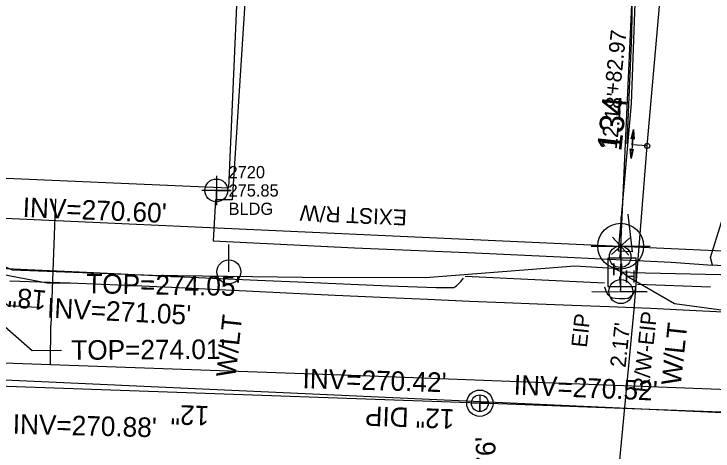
# Model space of a CAD drawing. Extents: x 2100323 to 2109811, y 740376 to 749755.
# Drawn here: x 2105501.9 to 2105644.7, y 741510.8 to 741600.1 of the extents above; entities that cross this region are included whole.
import ezdxf

# ---------------------------------------------------------------- set-up
doc = ezdxf.new("R2010")
doc.units = 0
for name, color, linetype in [('Cogo Default Point CELL', 7, 'Continuous'), ('COGO Default Point Number', 7, 'Continuous'), ('Exist Building', 7, 'Continuous'), ('Exist Building Cogo Elevation', 7, 'Continuous'), ('Exist Building Cogo Number', 7, 'Continuous'), ('Exist Building Cogo Point CELL', 7, 'Continuous'), ('Exist Horizontal Alignment', 7, 'Continuous'), ('Exist Other Culture Fence Line', 7, 'Continuous'), ('Exist Other Culture Gate', 7, 'Continuous'), ('Exist Property Corner CELL', 7, 'Continuous'), ('Exist Property Iron Pin CELL', 7, 'Continuous'), ('Exist Property Iron Pin Text', 7, 'Continuous'), ('Exist Property Line', 7, 'Continuous'), ('Exist Property Line Text', 7, 'Continuous'), ('Exist Property Tie Line Text', 7, 'Continuous'), ('Exist Right of Way Line', 7, 'Continuous'), ('Exist Right of Way Line Text', 7, 'Continuous'), ('Exist Roads Curbs', 7, 'Continuous'), ('Exist Roads EOP', 7, 'Continuous'), ('Exist Roads EOP Other', 7, 'Continuous'), ('Exist Structure Minor Catch Basin Top Elevation', 7, 'Continuous'), ('Exist Structure Minor Pipes RCP 18 Inch Invert', 7, 'Continuous'), ('Exist Structure Minor Pipes RCP 18 Inch Leader', 7, 'Continuous'), ('Exist Structure Minor Pipes RCP 18 Inch Text', 7, 'Continuous'), ('Exist Utilities Gas Change of Service SUE CELL', 7, 'Continuous'), ('Exist Utilities Gas UG Line SUE LOS B', 7, 'Continuous'), ('Exist Utilities Gas UG Line SUE LOS C', 7, 'Continuous'), ('Exist Utilities Other Pole Located Topo Text', 7, 'Continuous'), ('Exist Utilities Power Joint Use Telephone CELL', 7, 'Continuous'), ('Exist Utilities Power Pole CELL', 7, 'Continuous'), ('Exist Utilities Sanitary Sewer Manhole CELL', 7, 'Continuous'), ('Exist Utilities Sanitary Sewer Manhole Text', 7, 'Continuous'), ('Exist Utilities Sanitary Sewer UG Line', 7, 'Continuous'), ('Exist Utilities Sanitary Sewer UG Line Invert Elevation', 7, 'Continuous'), ('Exist Utilities Sanitary Sewer UG Line Text', 7, 'Continuous'), ('Exist Utilities TV Hand Hole CELL', 7, 'Continuous'), ('Exist Utilities TV UG Cable SUE LOS B', 7, 'Continuous'), ('Exist Utilities Water UG Line SUE LOS B', 7, 'Continuous')]:
    doc.layers.add(name, color=color, linetype=linetype)

msp = doc.modelspace()

# ---------------------------------------------------------------- linework, layer by layer
at = {"layer": 'Cogo Default Point CELL'}
for points in [[(2105625.85, 741558.64), (2105625.85, 741552.64)], [(2105619.85, 741552.64), (2105625.85, 741552.64)], [(2105625.85, 741552.64), (2105631.85, 741552.64)], [(2105625.85, 741552.64), (2105625.85, 741546.64)]]:
    msp.add_lwpolyline(points, dxfattribs=at)
msp.add_circle((2105625.85, 741552.64), 4.69, dxfattribs=at)
at = {"layer": 'Exist Building'}
msp.add_lwpolyline([(2105545.78, 741564.54), (2105550.54, 741673.25), (2105482.98, 741676.21), (2105478.21, 741567.5)], close=True, dxfattribs=at)
msp.add_lwpolyline([(2105627.15, 741573.57), (2105628.14, 741595.84), (2105628.48, 741616.26), (2105629.3, 741632.12), (2105629.94, 741650.5), (2105630.8, 741666.82), (2105631.43, 741673.37)], dxfattribs=at)
at = {"layer": 'Exist Building Cogo Point CELL'}
msp.add_lwpolyline([(2105543.23, 741567.03), (2105543.23, 741561.03), (2105543.23, 741564.03), (2105546.23, 741564.03), (2105540.23, 741564.03)], dxfattribs=at)
msp.add_circle((2105543.23, 741564.03), 2.34, dxfattribs=at)
at = {"layer": 'Exist Horizontal Alignment'}
msp.add_line((2105442.44, 741527.92), (2105877.12, 741508.21), dxfattribs=at)
at = {"layer": 'Exist Other Culture Fence Line'}
msp.add_lwpolyline([(2105628.25, 741551.48), (2105625.43, 741551.61), (2105628.08, 741581.82), (2105629.69, 741626.66), (2105633.02, 741680.11), (2105610.68, 741680.4), (2105612.37, 741710.75), (2105612.12, 741724.1), (2105613.19, 741740.31), (2105616.27, 741761.72), (2105642.19, 741758.96)], dxfattribs=at)
at = {"layer": 'Exist Other Culture Gate'}
msp.add_lwpolyline([(2105628.25, 741551.48), (2105627.39, 741559.15)], dxfattribs=at)
at = {"layer": 'Exist Property Corner CELL'}
msp.add_line((2105625.85, 741552.64), (2105625.85, 741552.64), dxfattribs=at)
msp.add_lwpolyline([(2105627.53, 741550.79), (2105624.17, 741554.49), (2105625.85, 741552.64), (2105624, 741550.95), (2105627.7, 741554.32)], dxfattribs=at)
at = {"layer": 'Exist Property Iron Pin CELL'}
for radius in [2.2, 0.0707]:
    msp.add_circle((2105625.75, 741550.47), radius, dxfattribs=at)
at = {"layer": 'Exist Property Line'}
for p, q in [((2105625.85, 741552.64), (2105631.31, 741670.03)), ((2105625.75, 741550.47), (2105625.85, 741552.64))]:
    msp.add_line(p, q, dxfattribs=at)
at = {"layer": 'Exist Right of Way Line'}
msp.add_line((2105478.64, 741559.31), (2105771.44, 741546.04), dxfattribs=at)
at = {"layer": 'Exist Roads Curbs'}
for points in [[(2105494.79, 741548.32), (2105504.65, 741547.84), (2105516.71, 741547.29), (2105529.36, 741546.72), (2105541, 741546.19), (2105551.66, 741545.69), (2105561.54, 741545.25), (2105570.69, 741544.87), (2105578.48, 741544.56), (2105584.27, 741544.35), (2105588.15, 741544.22), (2105590.61, 741544.17), (2105591.73, 741544.2), (2105591.99, 741544.3), (2105592.32, 741544.54), (2105593.18, 741545.44), (2105593.71, 741546.1)], [(2105628.88, 741544.19), (2105628.71, 741543.59), (2105628.55, 741543.17), (2105628.47, 741543.01), (2105628.28, 741542.75), (2105628.06, 741542.5), (2105627.81, 741542.26), (2105627.59, 741542.08), (2105627.39, 741541.96), (2105627.25, 741541.92), (2105626.67, 741541.88), (2105625.7, 741541.89), (2105624.75, 741541.94), (2105624.22, 741541.99), (2105624.12, 741542.02), (2105623.99, 741542.11), (2105623.79, 741542.24), (2105623.54, 741542.42), (2105623.42, 741542.53), (2105623.31, 741542.66), (2105623.11, 741542.97), (2105622.9, 741543.41), (2105622.67, 741544.03), (2105622.58, 741544.28)]]:
    msp.add_lwpolyline(points, dxfattribs=at)
at = {"layer": 'Exist Roads EOP'}
msp.add_lwpolyline([(2105501.01, 741545.53), (2105507.1, 741545.33), (2105513.38, 741545.11), (2105519.73, 741544.87), (2105526.52, 741544.59), (2105534.1, 741544.23), (2105542.38, 741543.82), (2105550.7, 741543.42), (2105558.95, 741543.03), (2105567.51, 741542.65), (2105576.74, 741542.22), (2105586.39, 741541.77), (2105594.94, 741541.39), (2105602.13, 741541.09), (2105608.83, 741540.83), (2105615.93, 741540.56), (2105623.49, 741540.27), (2105631.92, 741539.93), (2105641.3, 741539.5), (2105650.95, 741539.04)], dxfattribs=at)
at = {"layer": 'Exist Roads EOP Other'}
for p, q in [((2105594.04, 741546.5), (2105622.55, 741545.17)), ((2105629.28, 741544.88), (2105644.23, 741544.33))]:
    msp.add_line(p, q, dxfattribs=at)
for points in [[(2105550.01, 741661.23), (2105551.24, 741661.19), (2105550.57, 741634.09), (2105548.97, 741601.3), (2105546.93, 741569.53), (2105546.43, 741562.13), (2105543.08, 741562.08)], [(2105673.38, 741546.76), (2105644.61, 741548.75), (2105644.22, 741550.34), (2105648.65, 741564.57)], [(2105543.08, 741562.08), (2105542.57, 741553.75), (2105571.43, 741552.27), (2105596.13, 741551.26), (2105614.98, 741550.38), (2105636.14, 741549.36), (2105644.61, 741548.75)]]:
    msp.add_lwpolyline(points, dxfattribs=at)
at = {"layer": 'Exist Structure Minor Catch Basin Top Elevation'}
for points in [[(2105486.04, 741548.43), (2105505.59, 741531.34), (2105511.59, 741531.38)], [(2105493.58, 741548), (2105508.66, 741545.15), (2105514.66, 741545.04)]]:
    msp.add_lwpolyline(points, dxfattribs=at)
at = {"layer": 'Exist Structure Minor Pipes RCP 18 Inch Leader'}
msp.add_lwpolyline([(2105490.87, 741548.53), (2105500.69, 741540.48), (2105506.68, 741540.17)], dxfattribs=at)
at = {"layer": 'Exist Utilities Gas Change of Service SUE CELL'}
for p, q in [((2105628.45, 741576.51), (2105627.98, 741570.57)), ((2105628.2, 741573.39), (2105628.45, 741576.51)), ((2105631.27, 741573.14), (2105628.2, 741573.39)), ((2105631.27, 741573.14), (2105631.27, 741573.14))]:
    msp.add_line(p, q, dxfattribs=at)
for points in [[(2105628.45, 741576.51), (2105628.63, 741574.52), (2105628.32, 741574.97), (2105627.99, 741574.61)], [(2105627.98, 741570.57), (2105627.79, 741572.56), (2105628.1, 741572.11), (2105628.43, 741572.47)]]:
    msp.add_lwpolyline(points, close=True, dxfattribs=at)
msp.add_circle((2105631.27, 741573.14), 0.517, dxfattribs=at)
at = {"layer": 'Exist Utilities Gas UG Line SUE LOS B'}
msp.add_lwpolyline([(2105624.94, 741501.04), (2105628.62, 741539.68), (2105631.27, 741573.14)], dxfattribs=at)
at = {"layer": 'Exist Utilities Gas UG Line SUE LOS C'}
msp.add_lwpolyline([(2105631.27, 741573.14), (2105648.79, 741771.49), (2105653.34, 741770.68)], dxfattribs=at)
at = {"layer": 'Exist Utilities Power Joint Use Telephone CELL'}
msp.add_line((2105625.87, 741543.35), (2105625.87, 741543.35), dxfattribs=at)
msp.add_lwpolyline([(2105619.94, 741543.35), (2105631.27, 741543.31), (2105625.87, 741543.33), (2105625.87, 741548.97)], dxfattribs=at)
msp.add_circle((2105625.87, 741543.35), 2.45, dxfattribs=at)
at = {"layer": 'Exist Utilities Power Pole CELL'}
for q in [(2105545.79, 741553.01), (2105545.79, 741547.38)]:
    msp.add_line((2105545.79, 741547.38), q, dxfattribs=at)
msp.add_circle((2105545.79, 741547.38), 2.45, dxfattribs=at)
at = {"layer": 'Exist Utilities Sanitary Sewer Manhole CELL'}
msp.add_lwpolyline([(2105597.07, 741522.25), (2105597.07, 741518.82), (2105597.07, 741520.53), (2105598.78, 741520.53), (2105595.36, 741520.53)], dxfattribs=at)
for radius in [2.69, 1.71]:
    msp.add_circle((2105597.07, 741520.53), radius, dxfattribs=at)
at = {"layer": 'Exist Utilities Sanitary Sewer UG Line'}
for p, q in [((2105596.9, 741520.53), (2105443.36, 741525.95)), ((2105803.59, 741512.92), (2105597.21, 741520.52))]:
    msp.add_line(p, q, dxfattribs=at)
at = {"layer": 'Exist Utilities TV Hand Hole CELL'}
msp.add_line((2105626.12, 741547.29), (2105626.12, 741547.29), dxfattribs=at)
msp.add_lwpolyline([(2105623.24, 741544.42), (2105628.99, 741544.42), (2105628.99, 741550.17), (2105623.24, 741550.17), (2105623.24, 741544.42)], dxfattribs=at)
at = {"layer": 'Exist Utilities TV UG Cable SUE LOS B'}
for p in [(2105625.63, 741546.17), (2105625.87, 741543.35)]:
    msp.add_line(p, (2105625.79, 741543.83), dxfattribs=at)
for points in [[(2105627.84, 741547.28), (2105667.61, 741546.36), (2105692.99, 741545.5), (2105712.83, 741544.6), (2105737.43, 741542.97), (2105766.54, 741542.22), (2105781.76, 741544.99), (2105802.03, 741547.23), (2105819.47, 741550.78), (2105820.9, 741551.33), (2105821.13, 741552.42), (2105822.05, 741561.93), (2105822.61, 741596.31), (2105824.14, 741624.96), (2105825.03, 741672.82), (2105826.87, 741702.7), (2105829.59, 741729.26), (2105830, 741751.82), (2105833.25, 741777.15), (2105838.64, 741801.89), (2105847.18, 741832.98), (2105851.97, 741852.52)], [(2105469.55, 741565.07), (2105475.77, 741560.09), (2105489.56, 741552.97), (2105501.49, 741547.8), (2105530.19, 741546.7), (2105560.8, 741546.28), (2105585.99, 741546.21), (2105606.93, 741547.86), (2105616.48, 741548.63), (2105624.35, 741548.11)], [(2105624.35, 741548.11), (2105626.12, 741547.29), (2105625.63, 741546.17)], [(2105627.84, 741547.28), (2105626.12, 741547.29), (2105627.64, 741546.26)], [(2105627.64, 741546.26), (2105636.85, 741540.91), (2105657.5, 741538.09), (2105692.45, 741535.56), (2105713.59, 741534.37), (2105737.32, 741533.18), (2105773.37, 741532.46), (2105805.87, 741534.86), (2105829.01, 741536.01), (2105840.03, 741535.82)]]:
    msp.add_lwpolyline(points, dxfattribs=at)
at = {"layer": 'Exist Utilities Water UG Line SUE LOS B'}
for p in [(2105510.35, 741562.33), (2105509.34, 741528.46)]:
    msp.add_line(p, (2105509.43, 741536.45), dxfattribs=at)
msp.add_lwpolyline([(2105450.67, 741531.01), (2105471.1, 741529.78), (2105509.34, 741528.46), (2105574.6, 741526.15), (2105660.43, 741522.87), (2105670.77, 741523.08), (2105746.82, 741520.87), (2105774.67, 741519.48), (2105784.37, 741518.6), (2105791.45, 741518.35)], dxfattribs=at)

# ---------------------------------------------------------------- texts
at = {"layer": 'COGO Default Point Number'}
msp.add_text('134', height=5, rotation=83.8864, dxfattribs=at).set_placement((2105625.96, 741571.88))
at = {"layer": 'Exist Building Cogo Elevation'}
for s, p in [('275.85', (2105545.73, 741562.78)), ('BLDG', (2105545.73, 741559.03))]:
    msp.add_text(s, height=2.5, dxfattribs=at).set_placement(p)
at = {"layer": 'Exist Building Cogo Number'}
msp.add_text('2720', height=2.5, dxfattribs=at).set_placement((2105545.73, 741566.53))
at = {"layer": 'Exist Property Iron Pin Text'}
msp.add_text('EIP', height=3.2, rotation=83.8864, dxfattribs=at).set_placement((2105618.92, 741531.81))
at = {"layer": 'Exist Property Line Text'}
for s, p in [('R/W-EIP', (2105631.52, 741522.58)), ("2.17'", (2105626.84, 741527.72))]:
    msp.add_text(s, height=3.2, rotation=83.8864, dxfattribs=at).set_placement(p)
at = {"layer": 'Exist Property Tie Line Text'}
for s, p in [('+82.97', (2105625.65, 741583.53)), ("12.18'", (2105625.02, 741572.35))]:
    msp.add_text(s, height=3.2, rotation=83.8864, dxfattribs=at).set_placement(p)
at = {"layer": 'Exist Right of Way Line Text'}
msp.add_text('EXIST R/W', height=3.2, rotation=177.4033, dxfattribs=at).set_placement((2105582.22, 741560.05))
at = {"layer": 'Exist Structure Minor Catch Basin Top Elevation'}
for s, rotation, p in [("TOP=274.05'", 358.9819, (2105516.62, 741543.01)), ("TOP=274.01'", 0.3623, (2105513.6, 741529.39))]:
    msp.add_text(s, height=4, rotation=rotation, dxfattribs=at).set_placement(p)
at = {"layer": 'Exist Structure Minor Pipes RCP 18 Inch Invert'}
for s, rotation, p in [("INV=270.60'", 357.6065, (2105503.59, 741558.62)), ("INV=271.05'", 357.032, (2105508.57, 741538.07)), ("INV=270.88'", 358.5614, (2105501.59, 741514.3))]:
    msp.add_text(s, height=4, rotation=rotation, dxfattribs=at).set_placement(p)
at = {"layer": 'Exist Structure Minor Pipes RCP 18 Inch Text'}
msp.add_text('18" RCP', height=4, rotation=174.9709, dxfattribs=at).set_placement((2105508.67, 741543.52))
at = {"layer": 'Exist Utilities Other Pole Located Topo Text'}
for p in [(2105547.15, 741525.68), (2105638.12, 741524.01)]:
    msp.add_text('W/LT', height=4, rotation=83.8864, dxfattribs=at).set_placement(p)
at = {"layer": 'Exist Utilities Sanitary Sewer Manhole Text'}
msp.add_text("TOP=276.76'", height=4, rotation=92.6009, dxfattribs=at).set_placement((2105601.57, 741482.33))
at = {"layer": 'Exist Utilities Sanitary Sewer UG Line Invert Elevation'}
for s, rotation, p in [("INV=270.42'", 358.399, (2105560.8, 741523.6)), ("INV=270.52'", 357.5089, (2105603.93, 741522.32))]:
    msp.add_text(s, height=4, rotation=rotation, dxfattribs=at).set_placement(p)
at = {"layer": 'Exist Utilities Sanitary Sewer UG Line Text'}
for s, p in [('12"', (2105541.83, 741519.93)), ('12" DIP', (2105591.92, 741519.28))]:
    msp.add_text(s, height=4, rotation=177.9782, dxfattribs=at).set_placement(p)
at = {"layer": 'Exist Utilities TV Hand Hole CELL'}
for p in [(2105624.03, 741546.65), (2105626.6, 741545.19)]:
    msp.add_text('H', height=2.5, dxfattribs=at).set_placement(p)

doc.saveas('drawing.dxf')
